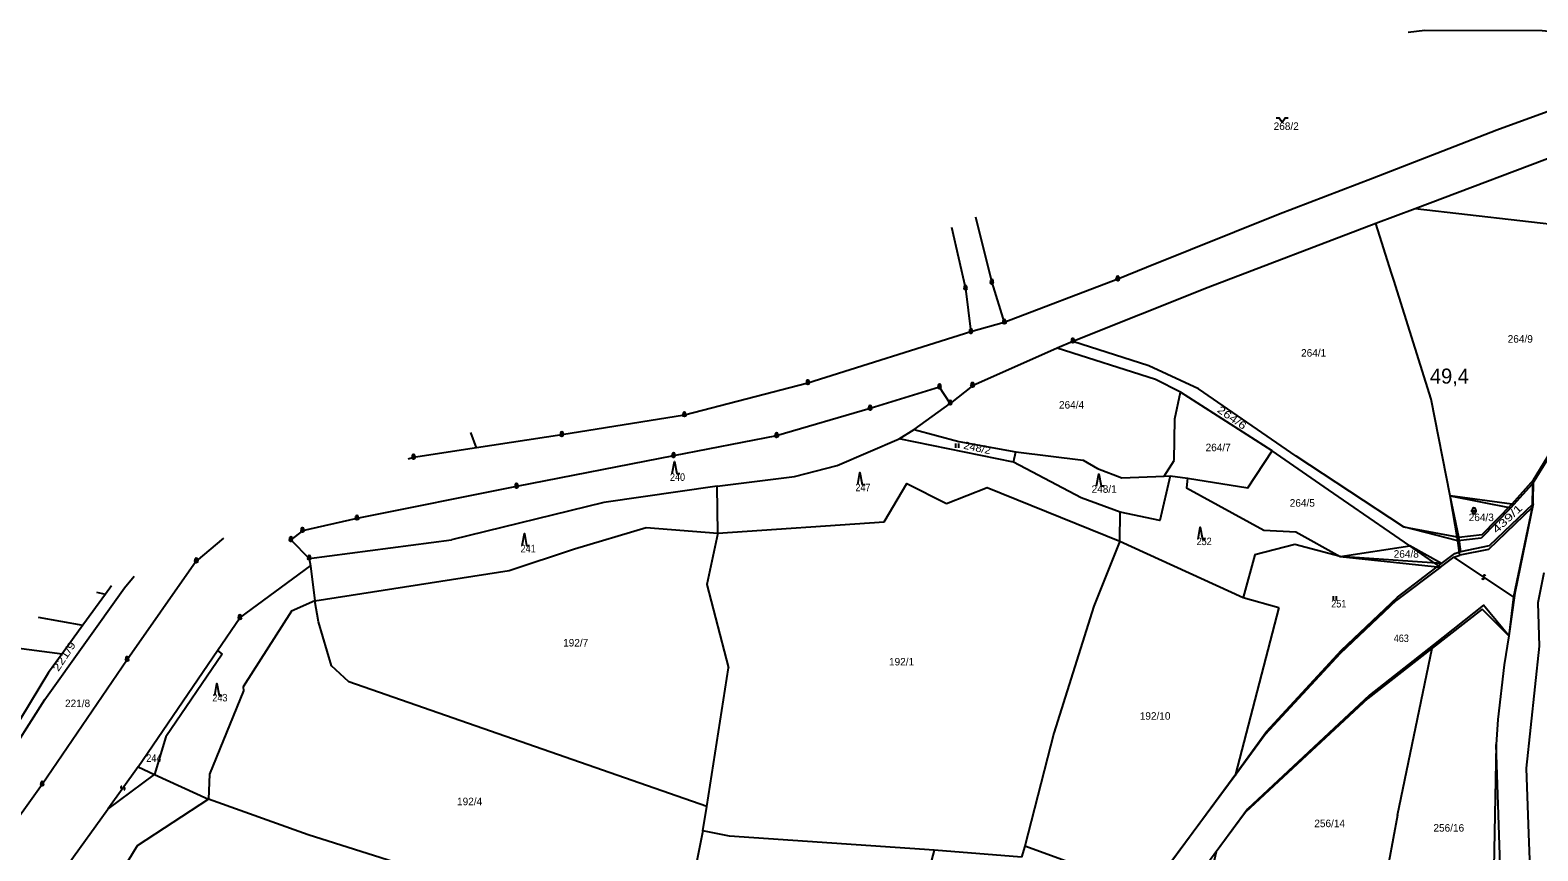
# Model space of a CAD drawing. Extents: x -680102 to -677253, y -1007548 to -1006096.
# Drawn here: x -678783 to -678281, y -1006617 to -1006344 of the extents above; entities that cross this region are included whole.
import ezdxf

# ---------------------------------------------------------------- set-up
doc = ezdxf.new("R2010")
doc.units = 0
for name, color, linetype, lineweight in [('1', 7, 'Continuous', 25), ('11', 7, 'Continuous', 25), ('24', 7, 'Continuous', 25), ('25', 7, 'Continuous', 25), ('4', 7, 'Continuous', 25)]:
    doc.layers.add(name, color=color, linetype=linetype, lineweight=lineweight)
doc.layers.add('18', color=7, linetype='Continuous')
doc.layers.add('56', color=7, linetype='Continuous')

msp = doc.modelspace()

# ---------------------------------------------------------------- linework, layer by layer
at = {"layer": '1'}
for p, q in [((-678324.47, -1006344.52), (-678318.91, -1006343.87)), ((-678267.26, -1006382.54), (-678322.15, -1006403.3)), ((-678322.15, -1006403.3), (-678335.2, -1006408.25)), ((-678246.7, -1006412.02), (-678322.15, -1006403.3)), ((-678335.2, -1006408.25), (-678391.05, -1006429.56)), ((-678421.15, -1006426.77), (-678458.91, -1006441.15)), ((-678441.25, -1006449.72), (-678469.49, -1006462.22)), ((-678410.82, -1006455.57), (-678436.06, -1006447.47)), ((-678469.49, -1006462.22), (-678476.92, -1006468.13)), ((-678480.47, -1006462.75), (-678503.59, -1006469.85)), ((-678476.92, -1006468.13), (-678480.47, -1006462.75)), ((-678503.59, -1006469.85), (-678534.69, -1006478.92)), ((-678488.86, -1006476.82), (-678476.92, -1006468.13)), ((-678634.61, -1006482.95), (-678636.48, -1006477.78)), ((-678534.69, -1006478.92), (-678568.99, -1006485.6)), ((-678283.05, -1006494.88), (-678273.17, -1006478.9)), ((-678655.57, -1006486.13), (-678657.36, -1006486.7)), ((-678568.99, -1006485.6), (-678621.29, -1006495.81)), ((-678455.82, -1006487.67), (-678455.05, -1006484.21)), ((-678405.63, -1006492.36), (-678402.31, -1006487.1)), ((-678351.03, -1006496.84), (-678369.7, -1006483.86)), ((-678621.29, -1006495.81), (-678674.39, -1006506.42)), ((-678554.24, -1006511.3), (-678554.49, -1006495.62)), ((-678307.93, -1006513.86), (-678310.51, -1006498.93)), ((-678674.39, -1006506.42), (-678692.51, -1006510.5)), ((-678692.51, -1006510.5), (-678696.37, -1006513.56)), ((-678696.37, -1006513.56), (-678690.28, -1006519.75)), ((-678690.28, -1006519.75), (-678642.93, -1006513.52)), ((-678347.12, -1006519.11), (-678323.91, -1006515.59)), ((-678300.19, -1006512.94), (-678307.93, -1006513.86)), ((-678713.36, -1006539.54), (-678689.9, -1006522.18)), ((-678690.28, -1006519.75), (-678689.9, -1006522.18)), ((-678761.12, -1006531.01), (-678758.08, -1006531.58)), ((-678367.5, -1006536.07), (-678382.03, -1006592)), ((-678780.53, -1006539.31), (-678765.59, -1006541.92)), ((-678765.59, -1006541.92), (-678772.56, -1006551.5)), ((-678800.53, -1006547.85), (-678772.56, -1006551.5)), ((-678772.56, -1006551.5), (-678777.09, -1006557.74)), ((-678719.23, -1006551.6), (-678737.98, -1006579.08)), ((-678720.8, -1006550.42), (-678719.23, -1006551.6)), ((-678327.99, -1006605.23), (-678316.46, -1006549.62)), ((-678557.97, -1006602.33), (-678677.1, -1006560.81)), ((-678337.85, -1006566.38), (-678378.6, -1006604.2)), ((-678442.37, -1006577.92), (-678452.11, -1006615.47)), ((-678737.98, -1006579.08), (-678741.78, -1006591.66)), ((-678292.98, -1006647), (-678295.16, -1006581.68)), ((-678285.21, -1006589.54), (-678284.39, -1006611.4)), ((-678327.99, -1006605.23), (-678337.28, -1006654.25)), ((-678284.39, -1006611.4), (-678278.02, -1006780.4))]:
    msp.add_line(p, q, dxfattribs=at)
for points in [[(-678318.91, -1006343.87), (-678279.85, -1006344.02), (-678234.53, -1006348.36), (-678236.56, -1006356.81), (-678243.14, -1006358.35), (-678294.96, -1006377.2)], [(-678294.96, -1006377.2), (-678336.38, -1006393.2), (-678367.58, -1006405.25)], [(-678468.5, -1006406.03), (-678463.04, -1006427.9), (-678458.91, -1006441.15), (-678470.03, -1006444.3)], [(-678367.58, -1006405.25), (-678411.56, -1006422.92), (-678421.15, -1006426.77)], [(-678476.44, -1006409.42), (-678471.83, -1006429.87), (-678470.03, -1006444.3), (-678524.27, -1006461.34), (-678565.41, -1006472.03), (-678606.19, -1006478.64)], [(-678310.51, -1006498.93), (-678316.86, -1006466.7), (-678329.27, -1006427.15), (-678330.02, -1006424.75), (-678335.2, -1006408.25)], [(-678391.05, -1006429.56), (-678436.06, -1006447.47), (-678441.25, -1006449.72)], [(-678402.31, -1006487.1), (-678402.11, -1006473.21), (-678400.24, -1006464.34), (-678408.62, -1006460.19), (-678441.25, -1006449.72)], [(-678307.93, -1006513.86), (-678326.05, -1006509.2), (-678361.78, -1006485.71), (-678394.3, -1006463.24), (-678410.82, -1006455.57)], [(-678397.88, -1006493.04), (-678377.85, -1006496.26), (-678369.7, -1006483.86), (-678400.24, -1006464.34)], [(-678514.52, -1006488.82), (-678493.95, -1006479.87), (-678488.86, -1006476.82)], [(-678488.86, -1006476.82), (-678474.05, -1006480.75), (-678455.05, -1006484.21), (-678432.69, -1006487.06), (-678427.91, -1006489.81), (-678419.78, -1006492.94)], [(-678606.19, -1006478.64), (-678634.61, -1006482.95), (-678655.57, -1006486.13)], [(-678420.43, -1006513.99), (-678420.31, -1006504.28), (-678433.32, -1006499.54), (-678455.82, -1006487.67), (-678493.95, -1006479.87)], [(-678554.49, -1006495.62), (-678528.79, -1006492.41), (-678514.52, -1006488.82)], [(-678403.74, -1006492.28), (-678407.09, -1006507.08), (-678420.31, -1006504.28)], [(-678419.78, -1006492.94), (-678405.63, -1006492.36), (-678403.74, -1006492.28)], [(-678403.74, -1006492.28), (-678397.88, -1006493.04), (-678398.21, -1006496.27), (-678372.49, -1006510.28), (-678361.83, -1006510.84), (-678347.12, -1006519.11), (-678362.17, -1006515.05), (-678375.48, -1006518.51), (-678379.35, -1006532.79)], [(-678554.49, -1006495.62), (-678592.26, -1006501.16), (-678642.93, -1006513.52)], [(-678498.85, -1006507.53), (-678491.32, -1006494.81), (-678478.16, -1006501.4)], [(-678478.16, -1006501.4), (-678464.6, -1006496.08), (-678420.43, -1006513.99)], [(-678313.73, -1006522.63), (-678323.91, -1006515.59), (-678351.03, -1006496.84)], [(-678290.24, -1006502.94), (-678283.05, -1006494.88), (-678283.19, -1006502.8), (-678297.7, -1006516.72), (-678307.23, -1006518.66), (-678307.93, -1006513.86)], [(-678310.51, -1006498.93), (-678290.24, -1006502.94), (-678300.19, -1006512.94)], [(-678578.16, -1006509.39), (-678554.24, -1006511.3), (-678498.85, -1006507.53)], [(-678283.19, -1006502.8), (-678289.35, -1006532.55), (-678290.92, -1006545.55), (-678299.82, -1006536.57)], [(-678688.37, -1006533.84), (-678623.72, -1006523.76), (-678601.94, -1006516.57), (-678578.16, -1006509.39)], [(-678554.24, -1006511.3), (-678557.91, -1006528.39), (-678550.75, -1006556.1)], [(-678718.85, -1006512.96), (-678727.87, -1006520.67), (-678750.9, -1006553.44), (-678779.15, -1006594.96), (-678792.87, -1006614.12)], [(-678420.43, -1006513.99), (-678429.12, -1006535.58), (-678442.37, -1006577.92)], [(-678420.43, -1006513.99), (-678379.35, -1006532.79), (-678367.5, -1006536.07)], [(-678689.9, -1006522.18), (-678688.37, -1006533.84), (-678696.22, -1006537.31)], [(-678347.12, -1006519.11), (-678313.73, -1006522.63), (-678328.43, -1006533.75), (-678347.15, -1006551.37), (-678372.11, -1006578.3), (-678382.03, -1006592)], [(-678313.73, -1006522.63), (-678309.29, -1006519.33), (-678307.23, -1006518.66)], [(-678833.83, -1006641.55), (-678802.15, -1006601.31), (-678792.37, -1006588.89), (-678778.26, -1006566.69), (-678751.77, -1006529.49), (-678748.59, -1006525.66)], [(-678279.33, -1006524.56), (-678281.26, -1006534.47), (-678280.85, -1006548.98), (-678285.21, -1006589.54)], [(-678756.11, -1006528.88), (-678758.08, -1006531.58), (-678765.59, -1006541.92)], [(-678696.22, -1006537.31), (-678712.31, -1006562.47), (-678712.18, -1006563.81), (-678723.49, -1006591.56), (-678723.77, -1006599.91)], [(-678677.1, -1006560.81), (-678682.83, -1006555.46), (-678687.24, -1006540.86), (-678688.37, -1006533.84)], [(-678299.82, -1006536.57), (-678316.46, -1006549.62), (-678337.85, -1006566.38)], [(-678747.27, -1006589.15), (-678720.8, -1006550.42), (-678713.36, -1006539.54)], [(-678290.92, -1006545.55), (-678292.51, -1006555.17), (-678294.65, -1006573.35)], [(-678777.09, -1006557.74), (-678795.83, -1006588.55), (-678792.37, -1006588.89)], [(-678559.23, -1006610.41), (-678557.97, -1006602.33), (-678550.75, -1006556.1)], [(-678294.65, -1006573.35), (-678295.16, -1006581.68), (-678296.26, -1006640.29)], [(-678770.69, -1006621.83), (-678757.37, -1006603.24), (-678741.78, -1006591.66)], [(-678747.27, -1006589.15), (-678741.78, -1006591.66), (-678723.77, -1006599.91)], [(-678382.03, -1006592), (-678408.13, -1006627.15), (-678412.57, -1006633.12)], [(-678723.77, -1006599.91), (-678747.58, -1006615.43), (-678754.95, -1006627.57), (-678759.08, -1006651.17)], [(-678567.8, -1006652.87), (-678619.4, -1006633.56), (-678635.56, -1006629.14), (-678690.66, -1006611.71), (-678723.77, -1006599.91)], [(-678378.6, -1006604.2), (-678389.05, -1006618.29), (-678396.74, -1006628.67)], [(-678559.23, -1006610.41), (-678567.8, -1006652.87), (-678582.53, -1006725.83)], [(-678482.29, -1006616.83), (-678550.36, -1006612.19), (-678559.23, -1006610.41)], [(-678453.19, -1006619.16), (-678482.29, -1006616.83), (-678489.11, -1006642.57), (-678493.38, -1006670.87), (-678496.7, -1006709.02), (-678504.57, -1006775.64)], [(-678423.65, -1006625.83), (-678452.11, -1006615.47), (-678453.19, -1006619.16)]]:
    msp.add_lwpolyline(points, dxfattribs=at)
at = {"layer": '11'}
for p, q in [((-678307.61, -1006512.66), (-678310.51, -1006498.93)), ((-678326.05, -1006509.2), (-678307.61, -1006512.66)), ((-678313.38, -1006521.44), (-678347.12, -1006519.11))]:
    msp.add_line(p, q, dxfattribs=at)
for points in [[(-678282.79, -1006493.59), (-678272.96, -1006477.58), (-678249.68, -1006443.91)], [(-678306.89, -1006517.45), (-678297.37, -1006515.48), (-678282.9, -1006501.51), (-678282.79, -1006493.59), (-678289.95, -1006501.68)], [(-678282.9, -1006501.51), (-678288.96, -1006531.28), (-678290.92, -1006545.55), (-678299.42, -1006535.34), (-678316.02, -1006548.44), (-678337.35, -1006565.27), (-678377.98, -1006603.23), (-678388.38, -1006617.35), (-678391.25, -1006629.93), (-678396.04, -1006627.76), (-678400.89, -1006634.35), (-678411.85, -1006632.26)], [(-678313.38, -1006521.44), (-678308.95, -1006518.13), (-678306.89, -1006517.45), (-678307.61, -1006512.66), (-678299.87, -1006511.71), (-678289.95, -1006501.68), (-678310.51, -1006498.93)], [(-678629.37, -1006821.24), (-678621.16, -1006820.81), (-678615.98, -1006812), (-678606.18, -1006803.39), (-678599.89, -1006806.81), (-678585.58, -1006799.58), (-678580.93, -1006797.11), (-678567.41, -1006803.68), (-678562.49, -1006802.11), (-678541.67, -1006795.44), (-678513.57, -1006781.17), (-678503.38, -1006775.08), (-678493.85, -1006770.72), (-678466.57, -1006734.1), (-678454.36, -1006711.39), (-678411.85, -1006632.26), (-678407.43, -1006626.27), (-678381.45, -1006591.04), (-678371.57, -1006577.31), (-678346.7, -1006550.29), (-678328.04, -1006532.61), (-678313.38, -1006521.44), (-678323.91, -1006515.59)]]:
    msp.add_lwpolyline(points, dxfattribs=at)
at = {"layer": '24'}
for centre, radius in [((-678421.15, -1006426.77), 0.5), ((-678421.15, -1006426.77), 0.022), ((-678471.83, -1006429.87), 0.5), ((-678471.83, -1006429.87), 0.022), ((-678463.04, -1006427.9), 0.5), ((-678463.04, -1006427.9), 0.022), ((-678458.91, -1006441.15), 0.5), ((-678458.91, -1006441.15), 0.022), ((-678470.03, -1006444.3), 0.5), ((-678470.03, -1006444.3), 0.022), ((-678436.06, -1006447.47), 0.5), ((-678436.06, -1006447.47), 0.022), ((-678524.27, -1006461.34), 0.5), ((-678524.27, -1006461.34), 0.022), ((-678480.47, -1006462.75), 0.5), ((-678469.49, -1006462.22), 0.5), ((-678469.49, -1006462.22), 0.022), ((-678480.47, -1006462.75), 0.022), ((-678565.41, -1006472.03), 0.5), ((-678565.41, -1006472.03), 0.022), ((-678503.59, -1006469.85), 0.5), ((-678503.59, -1006469.85), 0.022), ((-678476.92, -1006468.13), 0.5), ((-678476.92, -1006468.13), 0.022), ((-678606.19, -1006478.64), 0.5), ((-678606.19, -1006478.64), 0.022), ((-678534.69, -1006478.92), 0.5), ((-678534.69, -1006478.92), 0.022), ((-678655.57, -1006486.13), 0.5), ((-678655.57, -1006486.13), 0.022), ((-678568.99, -1006485.6), 0.5), ((-678568.99, -1006485.6), 0.022), ((-678621.29, -1006495.81), 0.5), ((-678621.29, -1006495.81), 0.022), ((-678674.39, -1006506.42), 0.5), ((-678674.39, -1006506.42), 0.022), ((-678692.51, -1006510.5), 0.5), ((-678692.51, -1006510.5), 0.022), ((-678696.37, -1006513.56), 0.5), ((-678696.37, -1006513.56), 0.022), ((-678727.87, -1006520.67), 0.5), ((-678727.87, -1006520.67), 0.022), ((-678690.28, -1006519.75), 0.5), ((-678690.28, -1006519.75), 0.022), ((-678713.36, -1006539.54), 0.5), ((-678713.36, -1006539.54), 0.022), ((-678750.9, -1006553.44), 0.5), ((-678750.9, -1006553.44), 0.022), ((-678779.15, -1006594.96), 0.5), ((-678779.15, -1006594.96), 0.022)]:
    msp.add_circle(centre, radius, dxfattribs=at)
for centre in [(-678463.041, -1006427.337), (-678421.151, -1006426.207), (-678471.831, -1006429.307), (-678458.911, -1006440.587), (-678470.031, -1006443.737), (-678436.061, -1006446.907), (-678524.271, -1006460.777), (-678480.471, -1006462.187), (-678469.491, -1006461.657), (-678476.921, -1006467.567), (-678565.411, -1006471.467), (-678503.591, -1006469.287), (-678606.191, -1006478.077), (-678534.691, -1006478.357), (-678655.571, -1006485.567), (-678568.991, -1006485.037), (-678621.291, -1006495.247), (-678674.391, -1006505.857), (-678696.371, -1006512.997), (-678692.511, -1006509.937), (-678727.871, -1006520.107), (-678690.281, -1006519.187), (-678713.361, -1006538.977), (-678750.901, -1006552.877), (-678779.151, -1006594.397)]:
    msp.add_arc(centre, 0.437, 328.35109, 209.97456, dxfattribs=at)
at = {"layer": '25'}
for p, q in [((-678475.067, -1006482.945), (-678475.067, -1006481.445)), ((-678474.033, -1006482.945), (-678474.033, -1006481.445)), ((-678303.55, -1006503.85), (-678301.55, -1006503.85)), ((-678303.05, -1006504.35), (-678303.05, -1006503.35)), ((-678302.05, -1006503.35), (-678302.05, -1006504.35)), ((-678349.317, -1006533.765), (-678349.317, -1006532.265)), ((-678348.283, -1006533.765), (-678348.283, -1006532.265))]:
    msp.add_line(p, q, dxfattribs=at)
for points in [[(-678368.37, -1006373.01), (-678367.37, -1006373.01), (-678366.37, -1006374.51), (-678365.37, -1006373.01), (-678364.37, -1006373.01)], [(-678569.44, -1006491.46), (-678568.69, -1006487.46), (-678567.94, -1006491.46), (-678566.94, -1006491.46)], [(-678507.7, -1006495.16), (-678506.95, -1006491.16), (-678506.2, -1006495.16), (-678505.2, -1006495.16)], [(-678428.21, -1006495.53), (-678427.46, -1006491.53), (-678426.71, -1006495.53), (-678425.71, -1006495.53)], [(-678619.42, -1006515.44), (-678618.67, -1006511.44), (-678617.92, -1006515.44), (-678616.92, -1006515.44)], [(-678394.4, -1006513.35), (-678393.65, -1006509.35), (-678392.9, -1006513.35), (-678391.9, -1006513.35)], [(-678721.75, -1006565.31), (-678721, -1006561.31), (-678720.25, -1006565.31), (-678719.25, -1006565.31)]]:
    msp.add_lwpolyline(points, dxfattribs=at)
for centre, radius, start, end in [((-678302.55, -1006503.35), 0.5, 0.101, 180.00143), ((-678302.55, -1006504.35), 0.5, 180.10243, 0.00286), ((-678299.525, -1006526.245), 0.368, 183.68874, 56.09417), ((-678299.113, -1006525.635), 0.369, 3.73143, 236.07976), ((-678752.617, -1006595.971), 0.369, 91.55729, 323.35057), ((-678752.023, -1006596.407), 0.367, 271.29774, 143.84779)]:
    msp.add_arc(centre, radius, start, end, dxfattribs=at)
at = {"layer": '4'}
for p, q in [((-678289.35, -1006532.55), (-678309.29, -1006519.33)), ((-678747.27, -1006589.15), (-678757.37, -1006603.24))]:
    msp.add_line(p, q, dxfattribs=at)

# ---------------------------------------------------------------- texts
at = {"layer": '18'}
for s, p in [('268/2', (-678369.24, -1006377.09)), ('264/9', (-678291.33, -1006447.9)), ('264/1', (-678360.11, -1006452.55)), ('264/4', (-678440.7, -1006469.84)), ('264/7', (-678391.89, -1006484.04)), ('248/1', (-678429.84, -1006497.88)), ('264/5', (-678363.88, -1006502.5)), ('264/3', (-678304.31, -1006507.3)), ('264/8', (-678329.28, -1006519.49)), ('192/7', (-678605.76, -1006549.05)), ('192/1', (-678497.28, -1006555.36)), ('221/8', (-678771.57, -1006569.22)), ('192/10', (-678413.81, -1006573.42)), ('192/4', (-678641.07, -1006601.88)), ('256/14', (-678355.7, -1006609.19)), ('256/16', (-678316.05, -1006610.67))]:
    msp.add_text(s, height=2.5, dxfattribs=at).set_placement(p)
for s, rotation, width, p in [('264/6', 325.003, 1.3, (-678388.282, -1006470.781)), ('248/2', 348.103, 1.1, (-678472.674, -1006483.176)), ('439/1', 43.3, 1.45, (-678295.022, -1006511.598)), ('221/9', 56.9, 1.3, (-678773.778, -1006557.584))]:
    msp.add_text(s, height=2.5, rotation=rotation, dxfattribs=dict(at, width=width)).set_placement(p)
at = {"layer": '18', "width": 0.9}
for s, p in [('240', (-678570.19, -1006493.9)), ('247', (-678508.47, -1006497.35)), ('241', (-678619.9, -1006517.7)), ('252', (-678394.88, -1006515.3)), ('251', (-678350.07, -1006536.04)), ('463', (-678329.26, -1006547.57)), ('243', (-678722.52, -1006567.33)), ('244', (-678744.51, -1006587.46))]:
    msp.add_text(s, height=2.5, dxfattribs=at).set_placement(p)
at = {"layer": '56'}
msp.add_text('49,4', height=5, dxfattribs=at).set_placement((-678317.23, -1006461.53))

doc.saveas('drawing.dxf')
